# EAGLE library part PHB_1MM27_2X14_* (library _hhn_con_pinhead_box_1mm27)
Pin Header Box-Type, 1.27mm/0.5"/50mil Pitch, 2x14 Circuits Note: see library description for an important note about THT-version
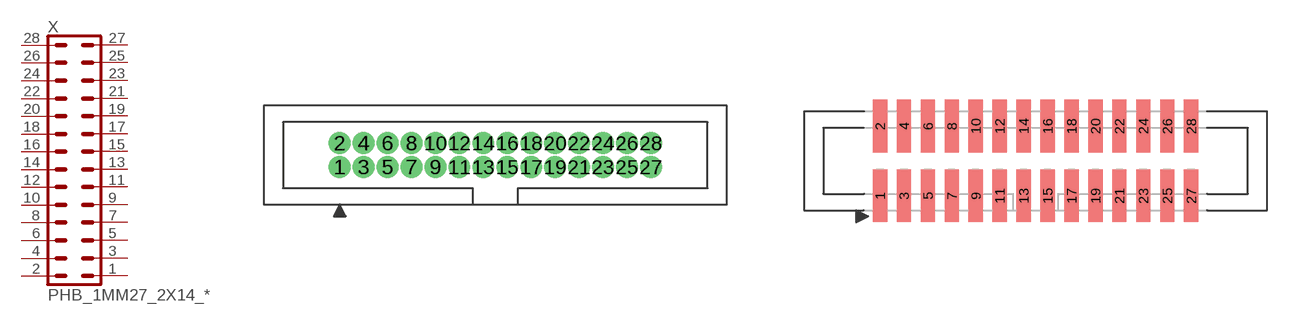
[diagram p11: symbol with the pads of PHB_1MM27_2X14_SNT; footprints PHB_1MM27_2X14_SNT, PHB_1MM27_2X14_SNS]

Designator prefix X

## PHB_1MM27_2X14_SNT  [PHB_1MM27_2X14_SNT]
1  1  pas
2  2  pas
3  3  pas
4  4  pas
5  5  pas
6  6  pas
7  7  pas
8  8  pas
9  9  pas
10  10  pas
11  11  pas
12  12  pas
13  13  pas
14  14  pas
15  15  pas
16  16  pas
17  17  pas
18  18  pas
19  19  pas
20  20  pas
21  21  pas
22  22  pas
23  23  pas
24  24  pas
25  25  pas
26  26  pas
27  27  pas
28  28  pas

## PHB_1MM27_2X14_SNS  [PHB_1MM27_2X14_SNS]
Pads as for PHB_1MM27_2X14_SNT

## Footprint PHB_1MM27_2X14_SNT (pad centres in mm)
Pin Header Box-Type, 1.27mm Pitch, 2x14 circuits, Straight, No Locking, THT Important Note: Diameter in this lbr is set to a specific value (NOT 'auto' = 0), this is ignored by actual eagle versions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
drill 0.65 pad 1 round: 1 -8.255,-0.635; 2 -8.255,0.635; 3 -6.985,-0.635; 4 -6.985,0.635; 5 -5.715,-0.635; 6 -5.715,0.635; 7 -4.445,-0.635; 8 -4.445,0.635; 9 -3.175,-0.635; 10 -3.175,0.635; 11 -1.905,-0.635; 12 -1.905,0.635; 13 -0.635,-0.635; 14 -0.635,0.635; 15 0.635,-0.635; 16 0.635,0.635; 17 1.905,-0.635; 18 1.905,0.635; 19 3.175,-0.635; 20 3.175,0.635; 21 4.445,-0.635; 22 4.445,0.635; 23 5.715,-0.635; 24 5.715,0.635; 25 6.985,-0.635; 26 6.985,0.635; 27 8.255,-0.635; 28 8.255,0.635

## Footprint PHB_1MM27_2X14_SNS (pad centres in mm)
Pin Header Box-Type, 1.27mm Pitch, 2x14 circuits, Straight, No Locking, SMT
smd 0.76 x 2.8: 1 -8.255,-1.85; 2 -8.255,1.85; 3 -6.985,-1.85; 4 -6.985,1.85; 5 -5.715,-1.85; 6 -5.715,1.85; 7 -4.445,-1.85; 8 -4.445,1.85; 9 -3.175,-1.85; 10 -3.175,1.85; 11 -1.905,-1.85; 12 -1.905,1.85; 13 -0.635,-1.85; 14 -0.635,1.85; 15 0.635,-1.85; 16 0.635,1.85; 17 1.905,-1.85; 18 1.905,1.85; 19 3.175,-1.85; 20 3.175,1.85; 21 4.445,-1.85; 22 4.445,1.85; 23 5.715,-1.85; 24 5.715,1.85; 25 6.985,-1.85; 26 6.985,1.85; 27 8.255,-1.85; 28 8.255,1.85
